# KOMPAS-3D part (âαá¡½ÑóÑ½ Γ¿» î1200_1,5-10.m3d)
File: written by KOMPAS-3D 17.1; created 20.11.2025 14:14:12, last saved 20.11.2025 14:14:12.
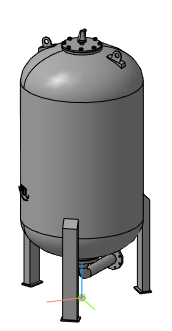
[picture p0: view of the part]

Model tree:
1. Операция без истории:2

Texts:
  REVIT MATERIAL OVERRIDDEN
  REVIT MATERIAL ID
  REVIT SUBCATEGORY ID
  REVIT CATEGORY ID
  REVIT ELEMENT ID
  REVIT BREP TAG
